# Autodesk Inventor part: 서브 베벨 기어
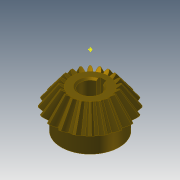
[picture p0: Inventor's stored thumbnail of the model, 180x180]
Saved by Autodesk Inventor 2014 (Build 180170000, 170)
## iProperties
Created: 2014-10
Part Number: 서브 베벨 기어
Material: 강철
Document SubType Name: Modeling
Designer: KYOUNG IL JANG
Categories: <?xml version="1.0" encoding="UTF-16"?> <MemberInstance><Categories><FamilyTemplate><FamilyTemplateParameter ValueType="xs:double" Id="1" ObjectReferenceKey="da
Mass: 134.694 g
Surface Area: 63.6518 cm^2
Volume: 17.1585 cm^3
Density: 7.85 g/cm^3
Appearance: 얼룩무늬
CustomPartVersion: 1
Company: 한국ATC센터
Author: KYOUNG IL JANG
Revision Number: 1
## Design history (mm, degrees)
node "맨 위 점"
node "메쉬 평면2"
sketch "톱니 본체 스케치"
  geometry: L1 (0, 0)-(18.003, -31.331); L2 (18.003, -31.331)-(21.664, -28.891); L3 (21.664, -28.891)-(0, 0); L4 (20, -30)-(0, 0); L5 (10.813, -18.818)-(13.012, -17.352); L6 (18.003, -31.331)-(10.813, -18.818); L7 (21.664, -28.891)-(13.012, -17.352); L8 (0, -39.387)-(0, 6.564) reference; L9 (0, -30)-(21.664, -30)
  constraints: 16 end point, 4 point on line, 3 perpendicular, 2 collinear, 1 horizontal alignment, 1 vertical alignment
  dimensions: "d0" = 40 diameter of L4.start L8 (= da_de); "d1" = 36.00616 diameter of L1.end L8 (= da_dfe); "d2" = 43.3282 diameter of L2.end L8 (= da_dae); "d3" = 14.4 distance between parallel lines of L2 L5 (= da_b); "d4" = 28.8906 vertical distance of L2.end L1.start (= da_ve)
revolve "톱니 본체" sketch "톱니 본체 스케치" stored, may be unused: angle "d5" = 90 deg
node "시작점"
node "톱니 평면"
sketch "시작 스케치"
  geometry: L1 (0, -23.505)-(0, 10.645) reference; L2 (-0.834, -2.928)-(0.834, -2.928); A1 r 8.898 centre (-9.698, -3.713) between (-0.834, -2.928) and (-3.903, 3.04); A2 r 8.898 centre (9.698, -3.713) between (3.903, 3.04) and (0.834, -2.928); A3 r 27.357 centre (0, -24.037) between (3.903, 3.04) and (-3.903, 3.04); 1 further point
  constraints: 6 point on circle, 3 centre point, 3 symmetric about line, 2 end point, 1 coincident, 1 perpendicular, 1 other
  dimensions: "d7" = 8.89846 radius of A1 (= fd_rr); "d8" = 9.69794 horizontal distance of point (0, -24.037) A1.centre (= fd_x); "d9" = 20.32439 vertical distance of point (0, -24.037) A1.centre (= fd_y); "d57" = 27.35701 radius of A3 (= 0.5 x fd_dva + 0.3 x da_he); "d58" = 21.10901 distance from line of A3.centre L2 (= 0.5 x fd_dva - 1.12 x da_he)
node "끝점"
  node "끝 평면"
sketch "3D 스케치 오른쪽"
  node "Helical Curve Right" dims "d65" = 229.90621 (computed from da_dm, da_delta, da_beta), "d66" = 31.5, "d67" = 40 (= da_de), "d68" = -5.88003 (= -da_delta), "d69" = 12.16458 (computed from fd_loft, da_delta)
node "끝 평면 오른쪽"
sketch "끝 스케치 오른쪽"
  geometry: L1 (0, -22.649)-(0, 12.15) reference; L2 (-0.497, -1.72)-(0.497, -1.72); A1 r 5.299 centre (-5.775, -2.187) between (-0.497, -1.72) and (-2.324, 1.834); A2 r 5.299 centre (5.775, -2.187) between (2.324, 1.834) and (0.497, -1.72); A3 r 16.291 centre (0, -14.29) between (2.324, 1.834) and (-2.324, 1.834); 1 further point
  constraints: 6 point on circle, 3 centre point, 3 symmetric about line, 2 end point, 1 coincident, 1 perpendicular, 1 other
  dimensions: "d70" = 5.77526 horizontal distance of A3.centre A1.centre (computed from fd_x, fd_ratio); "d71" = 12.10346 vertical distance of point (0, -14.29) A1.centre (computed from fd_y, fd_ratio); "d72" = 5.29916 radius of A1 (computed from fd_rr, fd_ratio); "d73" = 12.57071 distance from line of point (0, -14.29) L2 (computed from d58, fd_ratio); "d74" = 16.29149 radius of A3 (computed from d57, fd_ratio)
feature "로프트 오른쪽" sketch "끝 스케치 오른쪽" dims "d75" = 0, "d77" = 0, "d79" = 0, "d80" = 90 deg, "d85" = 20, "d92" = 90 deg, "d93" = 90 deg, "da_teethtype" = 0 [user parameter]
sketch "3D 스케치 왼쪽"
  node "Helical Curve Left" dims "d26" = 229.90621 (computed from da_dm, da_delta, da_beta), "d27" = 12.16458 (computed from fd_loft, da_delta), "d28" = 40 (= da_de), "d29" = -5.88003 (= -da_delta)
node "끝 평면 왼쪽"
sketch "끝 스케치 왼쪽" dims "d56" = 10.82768 (derived)
  geometry: L1 (0, -35.087)-(0, 18.089) reference; L2 (-0.497, -1.716)-(0.497, -1.716); A1 r 5.299 centre (-5.775, -2.183) between (-0.497, -1.716) and (-2.324, 1.838); A2 r 5.299 centre (5.775, -2.183) between (2.324, 1.838) and (0.497, -1.716); A3 r 16.291 centre (0, -14.287) between (2.324, 1.838) and (-2.324, 1.838); 2 further points; 1 other entity
  constraints: 6 point on circle, 3 centre point, 3 symmetric about line, 2 end point, 1 coincident, 2 other
  dimensions: "d30" = 5.29916 radius of A1 (computed from fd_rr, fd_ratio); "d31" = 5.77526 horizontal distance of point (0, -14.287) A1.centre (computed from fd_x, fd_ratio); "d32" = 12.10346 vertical distance of A1.centre point (0, -14.287) (computed from fd_y, fd_ratio); "d61" = 16.29149 radius of A3 (computed from d57, fd_ratio); "d62" = 12.57071 distance from line of point (0, -14.287) L2 (computed from d58, fd_ratio)
feature "로프트 왼쪽" sketch "끝 스케치 왼쪽" dims "d35" = 0, "d37" = 0, "d39" = 0, "d40" = 90 deg, "d84" = 10, "d90" = 90 deg, "d91" = 90 deg, "da_teethtype" = 0 [user parameter]
sketch "본체 스케치"
  geometry: L1 (0, -35.038)-(0, -19.531) reference; L2 (18.003, -31.331)-(10.813, -18.818) reference; L3 (10.813, -18.818)-(0, -18.818); L4 (18.003, -31.331)-(0, -31.331)
  constraints: 4 end point, 2 perpendicular, 2 point on line
revolve "본체 고정" sketch "본체 스케치" stored, may be unused: angle "d46" = 90 deg
feature "피치 지름" dims angle "d47" = 90 deg
sketch "스케치8"
  geometry: C1 r 17 at (0, 0); 1 further point
  constraints: 1 centre point, 1 coincident
  dimensions: "d94" = 34 diameter of C1
extrude "돌출1" join sketch "스케치8" distance "d95" = 10; taper "d96" = 0 deg
sketch "스케치9"
  geometry: 1 further point
hole "구멍1" sketch "스케치9" at (0, 0) diameter "d97" = 12; stored, may be unused: countersink angle "d101" = 90 deg, drill point angle "d103" = 118 deg; dims "d98" = 6, "d99" = 4, "d100" = 2, "d102" = 8
sketch "스케치10"
  geometry: 1 further point
sketch "스케치11"
  geometry: 1 further point
sketch "스케치12"
  geometry: L1 (-2, 5.657)-(-2, 7.8); L2 (-2, 7.8)-(2, 7.8); L3 (2, 7.8)-(2, 5.657); A1 r 6 centre (0, 0) between (-2, 5.657) and (2, 5.657) reference; 1 further point
  constraints: 6 end point, 2 parallel, 2 point on circle, 1 perpendicular, 1 vertical
  dimensions: "d104" = 4 distance of L1.end L2.end; "d105" = 13.8 dimension on A1 L2
extrude "돌출2" cut sketch "스케치12" stored distance "d106" = 7; taper "d107" = 0 deg
chamfer "모따기1" distance "d108" = 1; stored, may be unused: second distance "d109" = 2, angle "d110" = 45 deg
body "Solid1"
feature "로프트" dims "d17" = 0, "d18" = 90 deg, "d19" = 0, "d20" = 90 deg, "d89" = 0, "da_teethtype" = 0 [user parameter]
pattern_circular "원형 패턴" dims angle "d22" = 360 deg, "d88" = 0, "da_teethtype" = 0 [user parameter]
pattern_circular "원형 패턴 오른쪽" dims angle "d82" = 360 deg, "da_teethtype" = 0 [user parameter]
pattern_circular "원형 패턴 왼쪽" dims angle "d42" = 360 deg, "da_teethtype" = 0 [user parameter]
sketch "끝 스케치"
  geometry: L1 (0, -15.359)-(0, 6.983) reference; L2 (-0.497, -1.72)-(0.497, -1.72); A1 r 5.299 centre (-5.775, -2.187) between (-0.497, -1.72) and (-2.324, 1.834); A2 r 5.299 centre (5.775, -2.187) between (2.324, 1.834) and (0.497, -1.72); A3 r 16.291 centre (0, -14.29) between (2.324, 1.834) and (-2.324, 1.834); 1 further point
  constraints: 6 point on circle, 3 centre point, 3 symmetric about line, 2 end point, 1 coincident, 1 other
  dimensions: "d12" = 5.29916 radius of A1 (computed from fd_rr, fd_ratio); "d15" = 5.77526 horizontal distance of A1.centre point (0, -14.29) (computed from fd_x, fd_ratio); "d16" = 12.10346 vertical distance of A1.centre point (0, -14.29) (computed from fd_y, fd_ratio); "d59" = 16.29149 radius of A3 (computed from d57, fd_ratio); "d60" = 12.57071 distance from line of A3.centre L2 (computed from d58, fd_ratio)
sketch "Sketch6"
  geometry: L1 (20, -30)-(0, 0) reference; L2 (0, -37.8)-(0, 6.3) reference
body "Srf1"
other parameters: "da_b" = 14.4 [user parameter; used in 2 equation terms], "da_de" = 40 [user parameter; used in 4 equation terms], "da_dae" = 43.3282 [user parameter; used in 2 equation terms], "da_dfe" = 36.00616 [user parameter; used in 1 equation term], "da_le" = 36.05551 [user parameter; used in 1 equation term], "da_omega" = 90 deg [user parameter; used in 1 equation term], "da_beta" = 0 [user parameter; used in 2 equation terms], "da_delta" = 5.88003 [user parameter; used in 8 equation terms], "da_alpha" = 20 deg [user parameter; used in 2 equation terms], "da_he" = 4.4 [user parameter; used in 4 equation terms], "da_ve" = 28.8906 [user parameter; used in 1 equation term], "fd_dv" = 48.07402 (computed from da_de, da_delta) [user parameter; used in 1 equation term], "fd_dva" = 52.07402 (computed from da_dae, da_delta) [user parameter; used in 3 equation terms], "fd_dvb" = 45.1748 (computed from fd_dv, da_alpha) [user parameter; used in 2 equation terms], "da_zv" = 240.37008 [user parameter; used in 1 equation term], "fd_loft" = 14.62 (= da_b + 0.05 x da_he) [user parameter; used in 4 equation terms], "fd_ratio" = 5.95514 (computed from da_le, fd_loft) [user parameter; used in 15 equation terms], "fd_rr" = 8.89846 (computed from fd_dd, fd_dvb) [user parameter; used in 6 equation terms], "fd_angle" = 0.66075 (computed from da_zv) [user parameter; used in 4 equation terms], "fd_x1" = 1.58709 (computed from da_dvw, fd_angle) [user parameter; used in 1 equation term], "fd_y1" = 23.98456 (computed from da_dvw, fd_angle) [user parameter; used in 1 equation term], "fd_x2" = 8.11084 (computed from fd_rr, fd_angle2, fd_angle) [user parameter; used in 1 equation term], "fd_y2" = 3.66016 (computed from fd_rr, fd_angle2, fd_angle) [user parameter; used in 1 equation term], "fd_x" = 9.69794 (= fd_x1 + fd_x2) [user parameter; used in 4 equation terms], "fd_y" = 20.32439 (= fd_y1 - fd_y2) [user parameter; used in 4 equation terms], "fd_angle2" = 3.57832 (computed from fd_dvb, fd_dd, da_alpha) [user parameter; used in 2 equation terms], "fd_dd" = 48.55402 (= fd_dva - 0.8 x da_he) [user parameter; used in 2 equation terms], "da_dvw" = 48.07402 [user parameter; used in 2 equation terms], "d11" = 14.62 (= fd_loft), "da_dm" = 32.01232 [user parameter; used in 2 equation terms], "da_x" = 0 [user parameter], "da_m" = 2 [user parameter], "d48" = 0, "d49" = 0, "d50" = 90 deg (= da_omega), "d51" = 9 deg (computed from da_z), "d52" = 0, "d53" = 0, "d54" = 0
